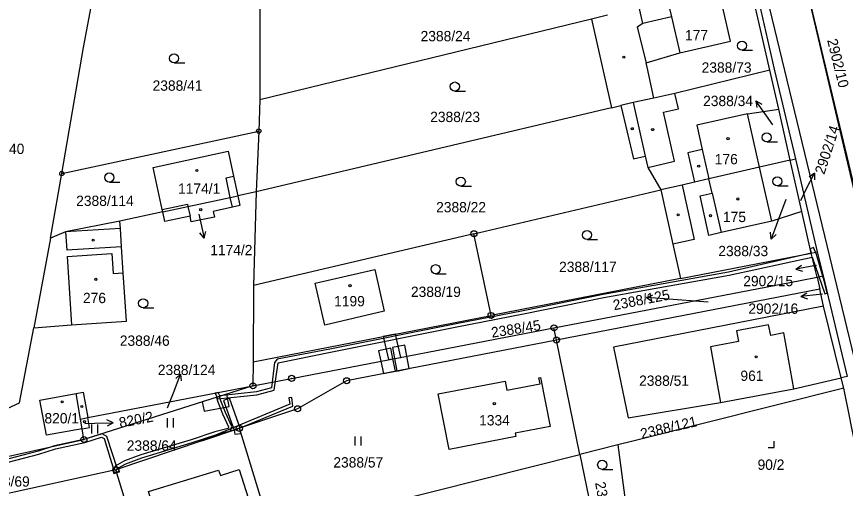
# Model space of a CAD drawing. Extents: x -758836 to -757729, y -1175316 to -1174366.
# Drawn here: x -758462.2 to -758325.7, y -1175090.9 to -1175013.2 of the extents above; entities that cross this region are included whole.
import ezdxf

# ---------------------------------------------------------------- set-up
doc = ezdxf.new("R2010")
doc.units = 0
for name, color, linetype in [('Hranice parcel', 7, 'Continuous'), ('Parcelní čísla', 7, 'Continuous'), ('Pop  PČ popisy', 7, 'Continuous'), ('Vnitřní kresba', 7, 'Continuous'), ('Věcná břemena k části', 7, 'Continuous'), ('Značky bodu BP', 7, 'Continuous'), ('Značky budov', 7, 'Continuous'), ('Značky kultur', 7, 'Continuous')]:
    doc.layers.add(name, color=color, linetype=linetype)

msp = doc.modelspace()

# ---------------------------------------------------------------- linework, layer by layer
at = {"layer": 'Hranice parcel'}
for p, q in [((-758338.16, -1175021.98), (-758341.49, -1175007.47)), ((-758422.18, -1175010.77), (-758422.16, -1175026.87)), ((-758364.93, -1175012.95), (-758367.53, -1175013.58)), ((-758367.53, -1175013.58), (-758422.16, -1175026.87)), ((-758367.53, -1175013.58), (-758364.25, -1175028.17)), ((-758336.71, -1175028.44), (-758338.16, -1175021.98)), ((-758364.25, -1175028.17), (-758422.76, -1175042.05)), ((-758422.16, -1175026.87), (-758422.36, -1175032.02)), ((-758364.25, -1175028.17), (-758362.74, -1175027.81)), ((-758334.82, -1175036.8), (-758336.71, -1175028.44)), ((-758454.79, -1175039.02), (-758422.36, -1175032.02)), ((-758422.36, -1175032.02), (-758422.76, -1175042.05)), ((-758334.82, -1175036.8), (-758339.87, -1175037.99)), ((-758334.82, -1175036.8), (-758333.96, -1175036.62)), ((-758332.92, -1175045.26), (-758334.82, -1175036.8)), ((-758333.96, -1175036.62), (-758330.37, -1175051.89)), ((-758456.63, -1175049.65), (-758454.79, -1175039.02)), ((-758386.92, -1175048.94), (-758356.15, -1175041.72)), ((-758422.76, -1175042.05), (-758425.82, -1175042.7)), ((-758422.76, -1175042.05), (-758423.24, -1175057.45)), ((-758438.18, -1175045.35), (-758445.21, -1175046.85)), ((-758331.37, -1175052.13), (-758332.92, -1175045.26)), ((-758456.63, -1175049.65), (-758459.42, -1175064.46)), ((-758386.92, -1175048.94), (-758423.24, -1175057.45)), ((-758384.09, -1175062.4), (-758386.92, -1175048.94)), ((-758352.88, -1175056.32), (-758331.37, -1175052.13)), ((-758331.37, -1175052.13), (-758330.37, -1175051.89)), ((-758330.41, -1175056.09), (-758331.37, -1175052.13)), ((-758330.37, -1175051.89), (-758329.39, -1175055.87)), ((-758352.88, -1175056.32), (-758384.09, -1175062.4)), ((-758330.41, -1175056.09), (-758329.39, -1175055.87)), ((-758330.41, -1175056.09), (-758329.96, -1175058.06)), ((-758329.39, -1175055.87), (-758325.44, -1175072.46)), ((-758423.24, -1175057.45), (-758423.3, -1175070.03)), ((-758329.96, -1175058.06), (-758373.32, -1175066.46)), ((-758329.33, -1175060.85), (-758329.96, -1175058.06)), ((-758326.41, -1175072.69), (-758329.33, -1175060.85)), ((-758423.3, -1175070.03), (-758384.09, -1175062.4)), ((-758373.32, -1175066.46), (-758373.73, -1175064.44)), ((-758373.32, -1175066.46), (-758407.89, -1175073.16)), ((-758369.46, -1175085.29), (-758373.32, -1175066.46)), ((-758423.3, -1175070.03), (-758423.32, -1175073.99)), ((-758334.22, -1175074.5), (-758326.41, -1175072.69)), ((-758325.44, -1175072.46), (-758326.41, -1175072.69)), ((-758326.01, -1175074.36), (-758326.41, -1175072.69)), ((-758423.32, -1175073.99), (-758451.15, -1175082.83)), ((-758450.52, -1175079.23), (-758423.32, -1175073.99)), ((-758346.32, -1175076.76), (-758334.22, -1175074.5)), ((-758451.15, -1175082.83), (-758451.45, -1175081.08)), ((-758415.92, -1175112.41), (-758425.55, -1175080.99)), ((-758363.2, -1175083.72), (-758369.46, -1175085.29)), ((-758363.2, -1175083.72), (-758361.58, -1175096.29)), ((-758369.46, -1175085.29), (-758366.71, -1175098.73)), ((-758445.89, -1175087.81), (-758470.38, -1175093.24))]:
    msp.add_line(p, q, dxfattribs=at)
for points in [[(-758297.14, -1175157.07), (-758301.82, -1175137.17), (-758334.58, -1174998.03), (-758360.35, -1174888.27), (-758361.81, -1174882.07)], [(-758354.19, -1174947.79), (-758350.83, -1174962.63), (-758347.5, -1174977.35), (-758344.08, -1174992.47), (-758340.74, -1175007.26), (-758337.45, -1175021.81), (-758333.96, -1175036.62)], [(-758454.79, -1175039.02), (-758451.2, -1175018.23), (-758447.49, -1174998.37), (-758446.54, -1174994.59)], [(-758357.3, -1175026.59), (-758358.38, -1175021.51), (-758358.56, -1175020.81), (-758353, -1175019.16), (-758344.66, -1175017.24), (-758346.66, -1175008.52)], [(-758338.16, -1175021.98), (-758353.81, -1175025.81), (-758357.3, -1175026.59)], [(-758357.3, -1175026.59), (-758360.67, -1175027.34), (-758362.74, -1175027.81)], [(-758362.74, -1175027.81), (-758360.65, -1175036.59), (-758358.69, -1175036.15), (-758358.27, -1175038), (-758356.15, -1175041.72)], [(-758339.87, -1175037.99), (-758341.86, -1175029.19), (-758336.71, -1175028.44)], [(-758438.18, -1175045.35), (-758438.27, -1175044.95), (-758439.76, -1175038.01), (-758427.42, -1175035.36), (-758426.52, -1175039.47), (-758425.82, -1175042.7)], [(-758339.87, -1175037.99), (-758348.2, -1175039.91), (-758350.61, -1175040.45), (-758352.63, -1175040.93), (-758356.15, -1175041.72)], [(-758332.92, -1175045.26), (-758337.86, -1175046.85), (-758339.87, -1175037.99)], [(-758356.15, -1175041.72), (-758354.15, -1175050.64), (-758352.88, -1175056.32)], [(-758425.82, -1175042.7), (-758425.48, -1175044.3), (-758426.7, -1175044.56), (-758429.86, -1175045.25), (-758429.67, -1175046.18), (-758433.47, -1175046.99), (-758433.67, -1175046.05), (-758437.83, -1175046.94), (-758438.18, -1175045.35)], [(-758438.18, -1175045.35), (-758434.01, -1175044.46), (-758427.04, -1175042.96), (-758425.82, -1175042.7)], [(-758459.42, -1175064.46), (-758453.17, -1175063.97), (-758444.16, -1175063.35), (-758444.71, -1175055.38), (-758444.96, -1175051.07), (-758445.14, -1175048.05), (-758445.21, -1175046.85)], [(-758445.21, -1175046.85), (-758454.19, -1175048.61), (-758456.63, -1175049.65)], [(-758403.26, -1175054.83), (-758401.68, -1175061.71), (-758411.49, -1175063.99), (-758413.09, -1175057.08), (-758403.26, -1175054.83)], [(-758373.73, -1175064.44), (-758333.2, -1175056.63), (-758330.41, -1175056.09)], [(-758329.33, -1175060.85), (-758363.94, -1175067.64), (-758361.54, -1175079.26), (-758346.32, -1175076.76)], [(-758476.34, -1175080.74), (-758464.51, -1175078.07), (-758461.75, -1175076.79), (-758459.42, -1175064.46)], [(-758423.32, -1175073.99), (-758416.94, -1175072.76), (-758373.73, -1175064.44)], [(-758334.22, -1175074.5), (-758335.85, -1175065.28), (-758338.01, -1175065.68), (-758338.4, -1175063.92), (-758343.65, -1175064.93), (-758343.35, -1175066.68), (-758347.97, -1175067.59), (-758346.32, -1175076.76)], [(-758407.89, -1175073.16), (-758415.96, -1175077.77), (-758425.55, -1175080.99)], [(-758381.49, -1175074.69), (-758376.03, -1175073.65), (-758376.21, -1175072.67), (-758375.94, -1175072.63), (-758374.37, -1175080.71), (-758380.1, -1175081.81), (-758380, -1175082.36), (-758390.99, -1175084.49), (-758392.78, -1175075.33), (-758381.78, -1175073.21), (-758381.49, -1175074.69)], [(-758326.01, -1175074.36), (-758360.75, -1175083.1), (-758363.2, -1175083.72)], [(-758322.58, -1175091.33), (-758323.49, -1175086.82), (-758324.78, -1175080.41), (-758325.02, -1175079.25), (-758326.01, -1175074.36)], [(-758451.45, -1175081.08), (-758457.34, -1175082.12), (-758458.39, -1175076.34), (-758452.45, -1175075.26), (-758451.28, -1175075.05), (-758450.52, -1175079.23)], [(-758451.45, -1175081.08), (-758451.73, -1175079.46), (-758450.52, -1175079.23)], [(-758451.45, -1175081.08), (-758450.22, -1175080.86), (-758450.52, -1175079.23)], [(-758425.55, -1175080.99), (-758431.74, -1175083.06), (-758445.89, -1175087.81)], [(-758474.49, -1175088.01), (-758463.5, -1175085.57), (-758451.15, -1175082.83)], [(-758414.64, -1175108.08), (-758417.89, -1175097.49), (-758369.46, -1175085.29)], [(-758436.59, -1175118.23), (-758442.14, -1175100.06), (-758445.89, -1175087.81)], [(-758423.72, -1175093.65), (-758426.88, -1175094.66), (-758426.59, -1175095.6), (-758438.18, -1175099.13), (-758440.54, -1175091.38), (-758428.96, -1175087.86), (-758428.67, -1175088.79), (-758425.56, -1175087.78), (-758423.72, -1175093.65)]]:
    msp.add_lwpolyline(points, dxfattribs=at)
at = {"layer": 'Pop  PČ popisy'}
for p, q in [((-758338.75, -1175029.5), (-758340.47, -1175027.04)), ((-758340.47, -1175027.04), (-758339.49, -1175027.57)), ((-758340.47, -1175027.04), (-758340.31, -1175028.15)), ((-758337.67, -1175031.02), (-758338.75, -1175029.5)), ((-758332.17, -1175041.61), (-758330.81, -1175038.94)), ((-758330.81, -1175038.94), (-758331.71, -1175039.6)), ((-758330.81, -1175038.94), (-758330.82, -1175040.06)), ((-758333.09, -1175043.45), (-758332.17, -1175041.61)), ((-758335.57, -1175043.31), (-758336.94, -1175046.99)), ((-758432.21, -1175045.73), (-758431.99, -1175046.72)), ((-758431.99, -1175046.72), (-758431.37, -1175049.66)), ((-758336.94, -1175046.99), (-758337.97, -1175049.81)), ((-758431.37, -1175049.66), (-758431.08, -1175048.57)), ((-758431.37, -1175049.66), (-758432.06, -1175048.78)), ((-758337.97, -1175049.81), (-758338.09, -1175048.7)), ((-758337.97, -1175049.81), (-758337.15, -1175049.04)), ((-758333.88, -1175054.77), (-758332.98, -1175054.1)), ((-758330.92, -1175054.25), (-758333.88, -1175054.77)), ((-758333.88, -1175054.77), (-758332.8, -1175055.09)), ((-758330.49, -1175054.18), (-758330.92, -1175054.25)), ((-758358.5, -1175059.45), (-758357.47, -1175059.02)), ((-758355.51, -1175059.66), (-758358.5, -1175059.45)), ((-758358.5, -1175059.45), (-758357.54, -1175060.02)), ((-758333.05, -1175059.28), (-758332.1, -1175058.68)), ((-758330.06, -1175058.97), (-758333.05, -1175059.28)), ((-758333.05, -1175059.28), (-758332, -1175059.68)), ((-758329.48, -1175058.91), (-758330.06, -1175058.97)), ((-758348.36, -1175060.2), (-758355.51, -1175059.66)), ((-758436.29, -1175074.86), (-758435.22, -1175072.06)), ((-758435.22, -1175072.06), (-758436.04, -1175072.81)), ((-758435.22, -1175072.06), (-758435.11, -1175073.17)), ((-758437.36, -1175077.62), (-758436.29, -1175074.86)), ((-758446.34, -1175080.1), (-758447.35, -1175079.61)), ((-758451.01, -1175080.18), (-758449.34, -1175080.15)), ((-758449.34, -1175080.15), (-758446.34, -1175080.1)), ((-758446.34, -1175080.1), (-758447.33, -1175080.62))]:
    msp.add_line(p, q, dxfattribs=at)
at = {"layer": 'Vnitřní kresba'}
for p, q in [((-758334.58, -1174998.03), (-758301.51, -1175137.25)), ((-758303.3, -1175156.35), (-758341.2, -1174999.31)), ((-758355.01, -1175010.43), (-758354.37, -1175013.21)), ((-758359.08, -1175014.29), (-758359.72, -1175011.59)), ((-758359.08, -1175014.29), (-758360.03, -1175014.91)), ((-758354.37, -1175013.21), (-758359.08, -1175014.29)), ((-758354.37, -1175013.21), (-758353, -1175019.16)), ((-758360.03, -1175014.91), (-758358.56, -1175020.81)), ((-758353.24, -1175028.35), (-758353.81, -1175025.81)), ((-758360.67, -1175027.34), (-758358.69, -1175036.15)), ((-758355.72, -1175028.93), (-758353.24, -1175028.35)), ((-758353.89, -1175036.99), (-758355.72, -1175028.93)), ((-758341.86, -1175029.19), (-758350.2, -1175031.07)), ((-758350.2, -1175031.07), (-758349.3, -1175035.06)), ((-758349.3, -1175035.06), (-758351.71, -1175035.6)), ((-758351.71, -1175035.6), (-758350.61, -1175040.45)), ((-758349.3, -1175035.06), (-758348.2, -1175039.91)), ((-758358.27, -1175038), (-758353.89, -1175036.99)), ((-758427.73, -1175039.73), (-758426.52, -1175039.47)), ((-758427.04, -1175042.96), (-758427.73, -1175039.73)), ((-758347.67, -1175042.23), (-758348.2, -1175039.91)), ((-758352.63, -1175040.93), (-758350.65, -1175049.86)), ((-758426.7, -1175044.56), (-758427.04, -1175042.96)), ((-758349.65, -1175042.68), (-758347.67, -1175042.23)), ((-758348.22, -1175049.2), (-758349.65, -1175042.68)), ((-758347.67, -1175042.23), (-758346.2, -1175048.74)), ((-758438.27, -1175044.95), (-758434.1, -1175044.06)), ((-758434.1, -1175044.06), (-758434.01, -1175044.46)), ((-758434.01, -1175044.46), (-758433.67, -1175046.05)), ((-758337.86, -1175046.85), (-758346.2, -1175048.74)), ((-758445.14, -1175048.05), (-758454.19, -1175048.61)), ((-758454.19, -1175048.61), (-758453.99, -1175051.65)), ((-758350.65, -1175049.86), (-758354.15, -1175050.64)), ((-758346.2, -1175048.74), (-758348.22, -1175049.2)), ((-758444.96, -1175051.07), (-758453.99, -1175051.65)), ((-758453.92, -1175052.67), (-758446.56, -1175052.18)), ((-758453.92, -1175052.67), (-758453.17, -1175063.97)), ((-758446.56, -1175052.18), (-758446.32, -1175055.48)), ((-758446.32, -1175055.48), (-758444.71, -1175055.38)), ((-758451.73, -1175079.46), (-758452.45, -1175075.26))]:
    msp.add_line(p, q, dxfattribs=at)
at = {"layer": 'Věcná břemena k části'}
for points in [[(-758329.11, -1175058.81), (-758328.72, -1175058.7), (-758329.1, -1175057.07), (-758330.5, -1175052.36), (-758330.98, -1175051.22), (-758331.52, -1175051.45), (-758331.37, -1175052.13), (-758344.99, -1175055.27), (-758358.85, -1175057.73), (-758365.63, -1175058.95), (-758378.83, -1175061.62), (-758389.83, -1175063.8), (-758410.66, -1175067.95), (-758419.34, -1175069.61), (-758419.76, -1175070.15), (-758420.26, -1175074.32), (-758422.74, -1175074.96), (-758428.77, -1175075.62), (-758429.02, -1175075.09), (-758429.52, -1175075.18), (-758429.07, -1175076.16), (-758422.65, -1175075.46), (-758419.8, -1175074.72), (-758419.16, -1175070.2), (-758410.56, -1175068.44), (-758389.73, -1175064.29), (-758378.73, -1175062.11), (-758365.53, -1175059.45), (-758358.77, -1175058.23), (-758344.89, -1175055.76), (-758331.21, -1175052.8)], [(-758398.95, -1175069.3), (-758399.84, -1175065.46), (-758401.84, -1175065.85), (-758400.96, -1175069.68)], [(-758402.61, -1175068.2), (-758402.25, -1175069.93), (-758401.82, -1175071.98), (-758399.82, -1175071.6), (-758400.25, -1175069.55), (-758400.62, -1175067.78)], [(-758400.33, -1175067.65), (-758399.98, -1175069.49), (-758399.59, -1175071.55), (-758397.58, -1175071.16), (-758397.97, -1175069.11), (-758398.32, -1175067.27)], [(-758446.23, -1175087.88), (-758445.89, -1175087.81), (-758445.64, -1175087.73), (-758445.58, -1175087.55), (-758444.27, -1175086.82), (-758441.63, -1175085.86), (-758433.31, -1175083.34), (-758429.44, -1175082.04), (-758427, -1175081.43), (-758426.79, -1175080.69), (-758427.85, -1175078.39), (-758428.62, -1175076.46), (-758428.81, -1175075.73), (-758429.29, -1175075.89), (-758429.1, -1175076.62), (-758428.31, -1175078.59), (-758427.33, -1175080.73), (-758427.4, -1175081.01), (-758429.58, -1175081.56), (-758433.47, -1175082.86), (-758441.79, -1175085.38), (-758444.47, -1175086.36), (-758445.98, -1175087.21)], [(-758431.74, -1175083.06), (-758425.55, -1175080.99), (-758416.72, -1175077.32), (-758416.88, -1175075.91), (-758417.38, -1175075.96), (-758417.26, -1175077)], [(-758427.21, -1175077.39), (-758427.6, -1175075.35), (-758431.65, -1175076.63), (-758431.35, -1175078.18)], [(-758426.38, -1175081.27), (-758425.55, -1175080.99), (-758425.43, -1175080.95), (-758427.2, -1175076.05), (-758428.14, -1175076.39)], [(-758425.28, -1175081.87), (-758425.55, -1175080.99), (-758426.38, -1175081.27), (-758426.32, -1175081.93)], [(-758445.89, -1175087.81), (-758445.64, -1175087.73), (-758447.38, -1175082.35), (-758448.16, -1175081.88), (-758451.15, -1175082.83), (-758455.97, -1175083.9), (-758458.7, -1175084.76), (-758473.92, -1175088.73), (-758474.21, -1175088.81), (-758474.05, -1175089.28), (-758473.59, -1175089.16), (-758458.56, -1175085.24), (-758455.84, -1175084.38), (-758451.02, -1175083.31), (-758448.23, -1175082.43), (-758447.8, -1175082.69), (-758446.23, -1175087.88)], [(-758445.74, -1175088.29), (-758445.89, -1175087.81), (-758446.38, -1175087.92), (-758446.22, -1175088.43)], [(-758445.74, -1175088.29), (-758445.89, -1175087.81), (-758446.23, -1175087.88), (-758446.38, -1175087.92), (-758446.22, -1175088.43)], [(-758445.64, -1175087.73), (-758445.89, -1175087.81), (-758445.74, -1175088.29), (-758445.27, -1175088.14), (-758445.42, -1175087.65)], [(-758445.64, -1175087.73), (-758445.89, -1175087.81), (-758445.74, -1175088.29), (-758445.27, -1175088.14), (-758445.42, -1175087.65)]]:
    msp.add_lwpolyline(points, close=True, dxfattribs=at)
at = {"layer": 'Značky bodu BP'}
for centre, radius in [((-758422.36, -1175032.02), 0.35), ((-758422.36, -1175032.02), 0.0212), ((-758454.79, -1175039.02), 0.35), ((-758454.79, -1175039.02), 0.0212), ((-758386.92, -1175048.94), 0.5), ((-758386.92, -1175048.94), 0.0303), ((-758384.09, -1175062.4), 0.5), ((-758384.09, -1175062.4), 0.0303), ((-758373.73, -1175064.44), 0.5), ((-758373.73, -1175064.44), 0.0303), ((-758373.32, -1175066.46), 0.5), ((-758373.32, -1175066.46), 0.0303), ((-758416.94, -1175072.76), 0.5), ((-758416.94, -1175072.76), 0.0303), ((-758407.89, -1175073.16), 0.5), ((-758407.89, -1175073.16), 0.0303), ((-758423.32, -1175073.99), 0.5), ((-758423.32, -1175073.99), 0.0303), ((-758415.96, -1175077.77), 0.5), ((-758415.96, -1175077.77), 0.0303), ((-758425.55, -1175080.99), 0.5), ((-758425.55, -1175080.99), 0.0303), ((-758451.15, -1175082.83), 0.5), ((-758451.15, -1175082.83), 0.0303), ((-758445.89, -1175087.81), 0.5), ((-758445.89, -1175087.81), 0.0303)]:
    msp.add_circle(centre, radius, dxfattribs=at)
at = {"layer": 'Značky budov'}
for centre in [(-758362.24, -1175019.85), (-758360.84, -1175031.64), (-758357.47, -1175031.78), (-758345.07, -1175033.27), (-758349.9, -1175037.81), (-758432.56, -1175038.51), (-758343.44, -1175043.21), (-758431.91, -1175044.97), (-758353.27, -1175045.81), (-758347.94, -1175045.95), (-758449.63, -1175049.99), (-758449.19, -1175056.44), (-758407.33, -1175057.5), (-758340.42, -1175069.21), (-758454.73, -1175076.64), (-758451.5, -1175077.39), (-758383.56, -1175076.93), (-758451.06, -1175079.9)]:
    msp.add_circle(centre, 0.175, dxfattribs=at)
at = {"layer": 'Značky kultur'}
for p, q in [((-758342.76, -1175018.69), (-758341.01, -1175018.69)), ((-758436.3, -1175020.8), (-758434.55, -1175020.8)), ((-758390.06, -1175025.44), (-758388.31, -1175025.44)), ((-758338.69, -1175033.81), (-758336.94, -1175033.81)), ((-758446.96, -1175040.42), (-758445.21, -1175040.42)), ((-758389.08, -1175041.1), (-758387.33, -1175041.1)), ((-758336.93, -1175041.06), (-758335.18, -1175041.06)), ((-758368.29, -1175049.88), (-758366.54, -1175049.88)), ((-758393.22, -1175055.53), (-758391.47, -1175055.53)), ((-758441.39, -1175061.15), (-758439.64, -1175061.15)), ((-758437.38, -1175080.84), (-758437.38, -1175079.34)), ((-758436.38, -1175080.84), (-758436.38, -1175079.34)), ((-758449.85, -1175081.87), (-758449.85, -1175080.37)), ((-758448.85, -1175081.87), (-758448.85, -1175080.37)), ((-758406.5, -1175083.83), (-758406.5, -1175082.33)), ((-758405.5, -1175083.83), (-758405.5, -1175082.33)), ((-758338.47, -1175084.13), (-758337.47, -1175084.13)), ((-758337.47, -1175084.13), (-758337.47, -1175083.13)), ((-758365.79, -1175087.75), (-758364.04, -1175087.75))]:
    msp.add_line(p, q, dxfattribs=at)
for centre in [(-758342.76, -1175017.94), (-758436.3, -1175020.05), (-758390.06, -1175024.69), (-758338.69, -1175033.06), (-758446.96, -1175039.67), (-758389.08, -1175040.35), (-758336.93, -1175040.31), (-758368.29, -1175049.13), (-758393.22, -1175054.78), (-758441.39, -1175060.4), (-758365.79, -1175087)]:
    msp.add_circle(centre, 0.75, dxfattribs=at)

# ---------------------------------------------------------------- texts
at = {"layer": 'Parcelní čísla'}
for s, p in [('2388/24', (-758395.7, -1175017.23)), ('177', (-758352.15, -1175017.08)), ('2388/73', (-758349.41, -1175022.4)), ('2388/41', (-758439.84, -1175025.38)), ('2388/34', (-758349.17, -1175027.91)), ('2388/23', (-758394.12, -1175030.54)), ('2388/40', (-758469.18, -1175035.8)), ('176', (-758347.25, -1175037.5)), ('1174/1', (-758435.65, -1175042.35)), ('2388/114', (-758452.43, -1175044.36)), ('2388/22', (-758393.14, -1175045.41)), ('175', (-758345.9, -1175047.02)), ('1174/2', (-758430.35, -1175052.48)), ('2388/33', (-758346.67, -1175052.63)), ('2388/117', (-758372.89, -1175055.24)), ('2902/15', (-758342.56, -1175057.58)), ('2388/19', (-758397.29, -1175059.35)), ('276', (-758451.31, -1175060.37)), ('1199', (-758409.94, -1175060.89)), ('2902/16', (-758341.72, -1175062.13)), ('2388/46', (-758445.24, -1175067.4)), ('2388/124', (-758438.98, -1175072.21)), ('961', (-758343.02, -1175073.18)), ('2388/51', (-758359.71, -1175073.99)), ('820/1', (-758457.65, -1175080.18)), ('1334', (-758386.06, -1175080.52)), ('2388/64', (-758444.09, -1175084.69)), ('2388/57', (-758410.07, -1175087.45)), ('90/2', (-758340.2, -1175087.83)), ('2388/69', (-758468.29, -1175090.6))]:
    msp.add_text(s, height=1.7, dxfattribs=at).set_placement(p)
for s, rotation, p in [('2902/10', 284, (-758328.76, -1175017.05)), ('2902/14', 72, (-758329.21, -1175039.27)), ('2388/125', 11, (-758363.84, -1175061.56)), ('2388/45', 9, (-758383.93, -1175066.07)), ('820/2', 11, (-758445.19, -1175080.93)), ('2388/121', 13, (-758359.28, -1175082.75)), ('2387/7', 280, (-758366.97, -1175089.95))]:
    msp.add_text(s, height=1.7, rotation=rotation, dxfattribs=at).set_placement(p)

doc.saveas('drawing.dxf')
